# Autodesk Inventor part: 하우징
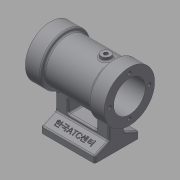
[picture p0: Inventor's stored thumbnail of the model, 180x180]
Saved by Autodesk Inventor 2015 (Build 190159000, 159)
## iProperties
Created: 2018-01
Part Number: 하우징
Material: 알루미늄 6061
Document SubType Name: Modeling
Designer: mduedu
Density: 2.71 g/cm^3
Appearance: 기본값
Mass: 74.6911 g
Surface Area: 127.588 cm^2
Volume: 27.5613 cm^3
Author: mduedu
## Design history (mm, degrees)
sketch "스케치1"
  geometry: L1 (-25, 0)-(25, 0); L2 (-25, 0)-(-25, 16); L3 (-25, 16)-(-15, 16); L4 (-15, 16)-(-15, 14); L5 (-15, 14)-(15, 14); L6 (15, 14)-(15, 16); L7 (15, 16)-(25, 16); L8 (25, 16)-(25, 0); 2 further points
  constraints: 16 end point, 3 parallel, 2 collinear, 2 perpendicular, 1 coincident, 1 horizontal, 1 midpoint, 1 vertical
  dimensions: "d0" = 50 distance of L1.start L1.end; "d2" = 10 distance of L2.end L3.end; "d3" = 10 distance of L6.end L7.end (= d2); "d4" = 32 diameter of L3 L1; "d5" = 28 diameter of L5 L1
revolve "회전1" sketch "스케치1" stored, may be unused: angle "d6" = 90 deg
hole "구멍1" diameter "d9" = 20; stored, may be unused: countersink angle "d13" = 90 deg, drill point angle "d15" = 118 deg; dims "d7" = 10, "d8" = 10, "d10" = 6, "d11" = 4, "d12" = 2, "d14" = 8
fillet "모깎기1" dims "d16" = 1
sketch "스케치2"
  geometry: L1 (0, 0)-(-34, 0); L2 (-34, 14)-(-34, -14); L3 (-34, 14)-(-30, 14); L4 (-30, 14)-(-26, 5); L5 (-26, 5)-(-13.077, 5); L6 (-26, -5)-(-13.077, -5); L7 (-30, -14)-(-26, -5); L8 (-34, -14)-(-30, -14); C1 r 10 at (0, 0) reference; A1 r 14 centre (0, 0) between (-13.077, 5) and (-13.077, -5); 2 further points
  constraints: 16 end point, 3 symmetric about line, 2 perpendicular, 2 point on circle, 1 centre point, 1 coincident, 1 horizontal, 1 midpoint, 1 parallel, 2 other
  dimensions: "d17" = 34 distance of L1.end L1.start; "d18" = 28 distance between parallel lines of L8 L3; "d19" = 10 distance between parallel lines of L6 L5; "d20" = 4 distance of L2.end L7.start; "d21" = 8 distance from line of L6.start L2
extrude "돌출1" join sketch "스케치2" stored distance "d22" = 34; taper "d23" = 0 deg
sketch "스케치3"
  geometry: L1 (-9, -16)-(9, -16); L2 (9, -16)-(9, -24); L3 (9, -24)-(-9, -24); L4 (-9, -24)-(-9, -16); L5 (-17, -15.199)-(-17, -26) reference; L6 (17, -26)-(17, -15.199) reference; L7 (-17, -34)-(17, -34) reference; 1 further point
  constraints: 8 end point, 2 parallel, 1 horizontal, 1 perpendicular
  dimensions: "d24" = 8 distance between parallel lines of L4 L5; "d25" = 8 distance between parallel lines of L2 L6; "d26" = 10 distance between parallel lines of L3 L7; "d27" = 8 distance of L1.end L2.end
extrude "돌출2" cut sketch "스케치3" stored distance "d28" = 34; taper "d29" = 0 deg
fillet "모깎기2" dims "d30" = 1
fillet "모깎기3" dims "d31" = 1
fillet "모깎기4" dims "d32" = 1
fillet "모깎기5" dims "d33" = 1
fillet "모깎기6" dims "d34" = 1
sketch "스케치4"
  geometry: 4 further points
  constraints: 4 other
hole "구멍2" sketch "스케치4" at (-12.5, 0), (0, -12.5), (12.5, 0), (0, 12.5) diameter "d35" = 2.459; stored, may be unused: countersink angle "d39" = 90 deg, drill point angle "d41" = 120 deg; dims "d36" = 5.5, "d37" = 4, "d38" = 2, "d40" = 7
sketch "스케치5"
  geometry: 4 further points
  constraints: 4 other
hole "구멍4" sketch "스케치5" at (-12.5, 0), (0, -12.5), (12.5, 0), (0, 12.5) diameter "d42" = 2.459; stored, may be unused: countersink angle "d46" = 90 deg, drill point angle "d48" = 120 deg; dims "d43" = 5.5, "d44" = 4, "d45" = 2, "d47" = 7
sketch "스케치6"
  geometry: 2 further points
  constraints: 2 other
hole "구멍5" sketch "스케치6" at (7, 14), (25, 14) diameter "d49" = 2.459; stored, may be unused: countersink angle "d53" = 90 deg, drill point angle "d55" = 120 deg; dims "d50" = 6.9, "d51" = 4, "d52" = 2, "d54" = 8.4
node "작업 평면1"
sketch "스케치7"
  geometry: L1 (-25, 16)-(-25, -16) reference; C1 r 3 at (-10, 0); 1 further point
  constraints: 1 centre point, 1 horizontal alignment
  dimensions: "d57" = 6 diameter of C1; "d60" = 15 distance from line of C1.centre L1
extrude "돌출3" join sketch "스케치7" stored distance "d61" = 10; taper "d62" = 0 deg
fillet "모깎기7" dims "d63" = 1
hole "구멍6" diameter "d66" = 2.459; stored, may be unused: countersink angle "d70" = 90 deg, drill point angle "d72" = 118 deg; dims "d64" = 10, "d65" = 10, "d67" = 6, "d68" = 4, "d69" = 2, "d71" = 8
sketch "스케치8"
  geometry: L1 (-1, 0)-(0, 0) reference; L2 (0, 0)-(0, 8.549) reference; L3 (0, 8.549)-(-1, 8.549) reference; L4 (-1, 8.549)-(-1, 0) reference; L5 (32, 0)-(33, 0) reference; L6 (33, 0)-(33, 8.549) reference; L7 (32, 8.549)-(33, 8.549) reference; L8 (32, 8.549)-(32, 0) reference; 3 further points
  constraints: 1 horizontal alignment, 1 midpoint, 1 vertical alignment, 1 other
feature "엠보싱1" sketch "스케치8" dims "d73" = 0.5, "d74" = 0
node "솔리드1"
node "투영된 루프1"
node "투영된 루프2"
node "절단 모서리 투영1"
other parameters: "d56" = 16
